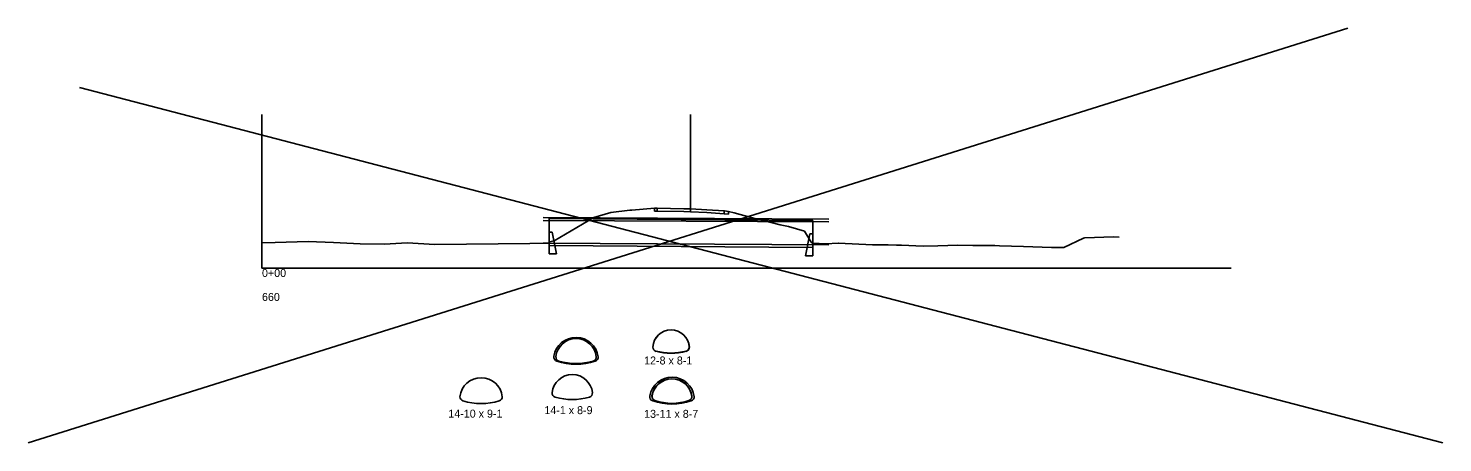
# Model space of a CAD drawing. Extents: x 153902 to 157473, y 413085 to 414252.
# Drawn here: x 155320.6 to 155815.6, y 413258.6 to 413403.9 of the extents above; entities that cross this region are included whole.
import ezdxf

# ---------------------------------------------------------------- set-up
doc = ezdxf.new("R2010")
doc.units = 0
for name, color, linetype in [('Default', 7, 'Continuous'), ('DR_X_Ditch', 7, 'Continuous'), ('DR_X_Storm_Sewer', 7, 'Continuous'), ('PV_X_Driveway', 7, 'Continuous'), ('RD_X_Cells', 7, 'Continuous'), ('RW_X_Esmt_CH', 7, 'Continuous'), ('RW_X_Esmt_SH', 7, 'Continuous'), ('RW_X_Text', 7, 'Continuous')]:
    doc.layers.add(name, color=color, linetype=linetype)

msp = doc.modelspace()

# ---------------------------------------------------------------- linework, layer by layer
at = {"layer": 'Default'}
for p, q in [((155782.38, 413403.89), (155320.58, 413258.6)), ((155338.55, 413383.14), (155815.56, 413258.6))]:
    msp.add_line(p, q, dxfattribs=at)
at = {"layer": 'DR_X_Ditch'}
for p, q in [((155502.87, 413337.17), (155595.1, 413336.49)), ((155502.87, 413337.17), (155502.87, 413324.79)), ((155595.1, 413324.11), (155595.1, 413336.49)), ((155502.87, 413332.46), (155503.87, 413332.46)), ((155503.87, 413332.46), (155505.46, 413324.79)), ((155594.1, 413331.78), (155592.52, 413324.11)), ((155595.1, 413331.78), (155594.1, 413331.78)), ((155502.87, 413327.75), (155595.1, 413327.07)), ((155502.87, 413324.79), (155505.46, 413324.79)), ((155595.1, 413324.11), (155592.52, 413324.11))]:
    msp.add_line(p, q, dxfattribs=at)
for centre, radius, start, end in [((155512.26, 413287.71), 7.83, 7.6258, 170.738), ((155505.99, 413288.64), 1.5, 167.2819, 251.5643), ((155512.26, 413307.44), 21.31, 251.5643, 288.4357), ((155518.52, 413288.64), 1.5, 288.4357, 4.1697), ((155545.84, 413273.75), 7.83, 7.6258, 170.738), ((155539.57, 413274.68), 1.5, 167.2819, 251.5643), ((155545.84, 413293.48), 21.31, 251.5643, 288.4357), ((155552.1, 413274.68), 1.5, 288.4357, 4.1697)]:
    msp.add_arc(centre, radius, start, end, dxfattribs=at)
at = {"layer": 'DR_X_Storm_Sewer'}
for p, q in [((155500.77, 413336.52), (155600.77, 413336.02)), ((155500.78, 413337.52), (155600.78, 413337.02)), ((155500.73, 413328.52), (155600.73, 413328.02))]:
    msp.add_line(p, q, dxfattribs=at)
at = {"layer": 'PV_X_Driveway'}
for p, q in [((155539.16, 413292.15), (155539.16, 413292.15)), ((155471.61, 413274.73), (155471.61, 413274.72)), ((155486.47, 413274.72), (155486.47, 413274.73)), ((155538.84, 413275.01), (155538.84, 413275.01)), ((155539.87, 413273.37), (155539.87, 413273.37)), ((155551.8, 413273.37), (155551.8, 413273.37)), ((155552.83, 413275.01), (155552.83, 413275.01))]:
    msp.add_line(p, q, dxfattribs=at)
for centre, radius, start, end in [((155545.52, 413291.77), 6.41, 3.4801, 176.5199), ((155545.52, 413291.77), 6.37, 3.4801, 176.5199), ((155512.26, 413288.04), 7.09, 6.1138, 173.8862), ((155540.66, 413292.15), 1.54, 180, 257.5397), ((155540.66, 413292.15), 1.5, 180, 257.5397), ((155550.38, 413292.15), 1.5, 282.4603, 0), ((155550.38, 413292.15), 1.54, 282.4603, 0), ((155506.7, 413288.68), 1.5, 175.5987, 253.6072), ((155512.26, 413307.56), 21.18, 253.6072, 286.3928), ((155517.81, 413288.68), 1.5, 286.3928, 4.4013), ((155545.52, 413311.5), 21.49, 255.7917, 284.2083), ((155545.52, 413311.5), 21.45, 255.7917, 284.2083), ((155479.04, 413273.94), 7.47, 6.1119, 173.8881), ((155510.96, 413275.42), 7.09, 6.1138, 173.8862), ((155545.84, 413273.97), 7.07, 8.4504, 171.5496), ((155545.84, 413273.97), 7.03, 8.4504, 171.5496), ((155505.41, 413276.06), 1.5, 175.5987, 253.6072), ((155516.52, 413276.06), 1.5, 286.3928, 4.4013), ((155473.11, 413274.74), 1.5, 180.6341, 253.1629), ((155479.04, 413293.52), 21.19, 252.5289, 287.4711), ((155484.97, 413274.74), 1.5, 286.8088, 359.3376), ((155510.96, 413294.94), 21.18, 253.6072, 286.3928), ((155540.37, 413274.83), 1.54, 173.1816, 251.1239), ((155540.37, 413274.83), 1.5, 173.1816, 251.1239), ((155545.84, 413290.81), 18.43, 251.1239, 288.8761), ((155545.84, 413290.81), 18.39, 251.1239, 288.8761), ((155551.3, 413274.83), 1.5, 288.8761, 6.8184), ((155551.3, 413274.83), 1.54, 288.8761, 6.8184)]:
    msp.add_arc(centre, radius, start, end, dxfattribs=at)
at = {"layer": 'RD_X_Cells'}
for p, q in [((155539.72, 413339.83), (155539.72, 413340.83)), ((155540.7, 413339.82), (155540.7, 413340.82)), ((155564.05, 413338.87), (155564.05, 413339.87)), ((155565.61, 413338.69), (155565.61, 413339.69))]:
    msp.add_line(p, q, dxfattribs=at)
msp.add_lwpolyline([(155539.72, 413339.83), (155539.73, 413339.83), (155539.82, 413339.83), (155540.27, 413339.83), (155540.71, 413339.82), (155550.04, 413339.63), (155552.36, 413339.59), (155558.02, 413339.26), (155564.06, 413338.87), (155564.26, 413338.85), (155565.61, 413338.69)], dxfattribs=at)
at = {"layer": 'RW_X_Esmt_CH'}
for q in [(155402.36, 413373.63), (155741.54, 413319.79)]:
    msp.add_line((155402.36, 413319.79), q, dxfattribs=at)
at = {"layer": 'RW_X_Esmt_SH'}
msp.add_lwpolyline([(155402.36, 413328.64), (155406.98, 413328.82), (155418.55, 413329.16), (155427.43, 413328.8), (155436.75, 413328.28), (155445.2, 413328.26), (155453.2, 413328.69), (155462.82, 413328.06), (155496.09, 413328.49), (155500.73, 413328.52), (155502.58, 413328.58), (155502.96, 413329.08), (155504.59, 413329.36), (155518.5, 413337.51), (155524.4, 413339.29), (155531.13, 413340.1), (155531.72, 413340.15), (155531.77, 413340.17), (155539.73, 413340.83), (155539.82, 413340.83), (155540.27, 413340.83), (155540.71, 413340.82), (155550.04, 413340.63), (155552.36, 413340.59), (155558.02, 413340.26), (155564.06, 413339.87), (155564.26, 413339.85), (155565.62, 413339.69), (155567.6, 413339.18), (155573.08, 413337.66), (155575.32, 413337.04), (155576.31, 413336.78), (155576.91, 413336.63), (155577.82, 413336.45), (155583.69, 413335), (155586.57, 413334.43), (155592.16, 413332.82), (155594.56, 413328.94), (155595.02, 413328.55), (155599.67, 413328.36), (155604.03, 413328.54), (155604.12, 413328.54), (155604.15, 413328.54), (155616.03, 413328.01), (155617.34, 413328), (155621.51, 413327.96), (155624.36, 413327.88), (155626.13, 413327.86), (155633.7, 413327.54), (155638.88, 413327.63), (155645.88, 413327.86), (155651.07, 413327.74), (155658.84, 413327.69), (155660.41, 413327.61), (155668.84, 413327.36), (155675.38, 413327.14), (155678.6, 413327.01), (155682.24, 413326.99), (155683, 413327), (155689.88, 413330.35), (155690.32, 413330.46), (155700.33, 413330.73), (155702.36, 413330.69)], dxfattribs=at)
at = {"layer": 'RW_X_Text'}
msp.add_line((155552.36, 413339.59), (155552.36, 413373.63), dxfattribs=at)

# ---------------------------------------------------------------- texts
at = {"layer": 'Default'}
for s, p in [('0+00', (155402.36, 413316.71)), ('660', (155402.36, 413308.31))]:
    msp.add_text(s, height=2.8, dxfattribs=at).set_placement(p)
at = {"layer": 'PV_X_Driveway'}
for s, p in [('12-8 x 8-1', (155536.09, 413286.04)), ('14-1 x 8-9', (155501.18, 413268.63)), ('14-10 x 9-1', (155467.57, 413267.41)), ('13-11 x 8-7', (155536.09, 413267.34))]:
    msp.add_text(s, height=2.8, dxfattribs=at).set_placement(p)

doc.saveas('drawing.dxf')
